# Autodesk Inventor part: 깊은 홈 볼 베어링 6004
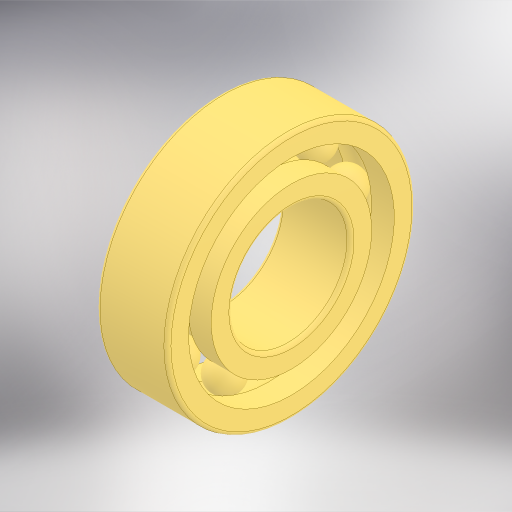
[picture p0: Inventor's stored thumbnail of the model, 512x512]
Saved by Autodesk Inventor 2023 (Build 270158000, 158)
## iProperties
Created: 2026-07
Part Number: 깊은 홈 볼 베어링 6004
Material: 강철, 연강
Description: 깊은 그루브 볼 베어링
Document SubType Name: Modeling
Designer: home
Density: 7.85 g/cm^3
Appearance: 기본값
Author: jhkim
Sending System: Autodesk Inventor 2027
Preprocessor: ST-DEVELOPER v20.1
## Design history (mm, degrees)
feature "Solid1"
feature "Solid1:1"
feature "Solid1:2"
feature "Solid1:3"
feature "Solid1:4"
feature "Solid1:5"
feature "Solid1:6"
feature "Solid1:7"
feature "Solid1:8"
feature "Solid1:9"
feature "Solid1:10"
node "솔리드1"
node "솔리드2"
node "솔리드3"
node "솔리드4"
node "솔리드5"
node "솔리드6"
node "솔리드7"
node "솔리드8"
node "솔리드9"
node "솔리드10"
node "솔리드11"
